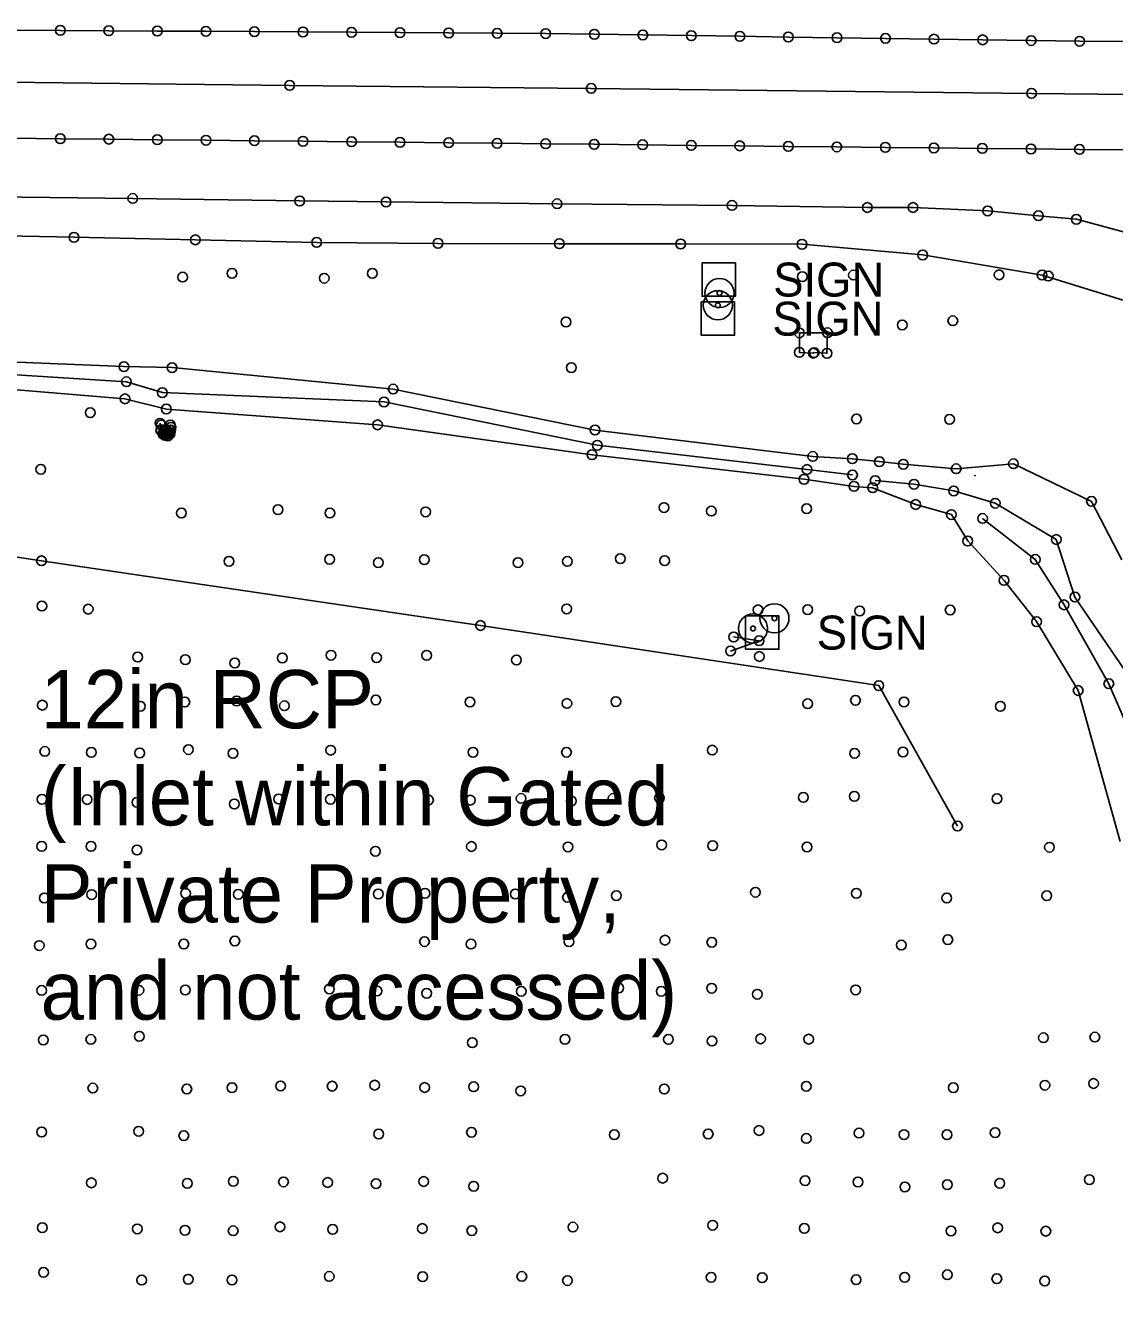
# Model space of a CAD drawing. Extents: x 20503438 to 20508873, y 7964251 to 7984667.
# Drawn here: x 20505827.9 to 20506052.3, y 7970296.1 to 7970558.9 of the extents above; entities that cross this region are included whole.
import ezdxf

# ---------------------------------------------------------------- set-up
doc = ezdxf.new("R2010")
doc.units = 0
for name, color, linetype in [('SurBreakLine', 7, 'Continuous'), ('SurConcreteSlab', 7, 'Continuous'), ('SurDrainageArrowDown', 7, 'Continuous'), ('SurDrainageArrowUp', 7, 'Continuous'), ('SurEdgeShoulderPaved', 7, 'Continuous'), ('SurEdgeShoulderUnpaved', 7, 'Continuous'), ('SurFenceChainLink', 7, 'Continuous'), ('SurMiscStructureLine', 7, 'Continuous'), ('SurPointsNonDTM', 7, 'Continuous'), ('SurRoadPoints', 7, 'Continuous'), ('SurSurveyPoints', 7, 'Continuous'), ('SurTopOfWater', 7, 'Continuous'), ('SurTxtDrainage', 7, 'Continuous')]:
    doc.layers.add(name, color=color, linetype=linetype)

msp = doc.modelspace()

# ---------------------------------------------------------------- linework, layer by layer
at = {"layer": 'SurBreakLine'}
for points in [[(20505659.98, 7970549.19), (20505725.91, 7970548.38), (20505788.99, 7970547.63), (20505882.34, 7970546.59), (20505944.46, 7970545.97), (20506035.17, 7970544.95), (20506055.65, 7970544.73), (20506135.76, 7970544.03), (20506246.7, 7970542.7), (20506314.1, 7970541.94), (20506377.13, 7970541.22), (20506448.59, 7970540.63), (20506494, 7970540.08), (20506513.48, 7970539.53), (20506534.35, 7970539.62)], [(20505710.77, 7970497.54), (20505732.85, 7970495.46), (20505756.48, 7970493.37), (20505802.57, 7970490.52), (20505848.21, 7970488.68), (20505858.14, 7970488.46), (20505903.67, 7970484.04), (20505945.27, 7970475.61), (20505990.11, 7970470.17), (20505998.24, 7970469.71), (20506003.81, 7970469.11), (20506008.75, 7970468.56), (20506019.64, 7970467.63), (20506031.44, 7970468.66), (20506047.52, 7970460.92), (20506053.76, 7970448.87)], [(20505711.46, 7970490.59), (20505731.01, 7970491.18), (20505758.81, 7970489.68), (20505801.32, 7970485.94), (20505848.43, 7970482.04), (20505856.97, 7970479.93), (20505900.46, 7970476.68), (20505944.64, 7970470.53), (20505988.31, 7970465.47), (20505998.59, 7970464), (20506002.44, 7970463.73), (20506011.31, 7970460.28), (20506018.66, 7970458.21), (20506022.02, 7970452.76), (20506029.51, 7970444.65), (20506036.2, 7970436.16), (20506044.77, 7970421.97), (20506053.42, 7970390.9)], [(20505857.84, 7970475.58), (20505857.72, 7970474.82), (20505857.29, 7970474.41), (20505856.69, 7970474.5), (20505856.27, 7970474.81), (20505855.82, 7970475.52), (20505855.65, 7970477.02)], [(20506002.96, 7970465.21), (20506010.95, 7970464.45), (20506019.15, 7970463.07), (20506027.69, 7970460.54), (20506040.26, 7970453.07), (20506044.1, 7970441.21), (20506055.37, 7970424.69), (20506067.63, 7970400.85), (20506090.73, 7970364.86), (20506121.5, 7970310.22), (20506143.59, 7970262.18), (20506176.03, 7970210.91), (20506203.05, 7970164.06), (20506235.78, 7970108.78), (20506259.31, 7970069.25), (20506303.96, 7969999.09)]]:
    msp.add_lwpolyline(points, dxfattribs=at)
at = {"layer": 'SurConcreteSlab'}
for points in [[(20506055.09, 7970555.65), (20506045.09, 7970555.68), (20506035.09, 7970555.82), (20506025.09, 7970555.97), (20506015.09, 7970556.11), (20506005.09, 7970556.26), (20505995.09, 7970556.4), (20505985.09, 7970556.55), (20505975.09, 7970556.69), (20505965.1, 7970556.83), (20505955.1, 7970556.98), (20505945.1, 7970557.12), (20505935.1, 7970557.26), (20505925.1, 7970557.32), (20505915.1, 7970557.39), (20505905.1, 7970557.45), (20505895.1, 7970557.52), (20505885.1, 7970557.59), (20505875.1, 7970557.65), (20505865.1, 7970557.72), (20505855.1, 7970557.78), (20505845.1, 7970557.85), (20505835.1, 7970557.92), (20505825.1, 7970557.98)], [(20505825.12, 7970535.72), (20505835.12, 7970535.61), (20505845.11, 7970535.51), (20505855.11, 7970535.4), (20505865.11, 7970535.3), (20505875.1, 7970535.19), (20505885.1, 7970535.08), (20505895.1, 7970534.98), (20505905.09, 7970534.87), (20505915.09, 7970534.77), (20505925.09, 7970534.66), (20505935.08, 7970534.56), (20505945.08, 7970534.45), (20505955.08, 7970534.35), (20505965.07, 7970534.24), (20505975.07, 7970534.14), (20505985.07, 7970534.03), (20505995.06, 7970533.92), (20506005.06, 7970533.82), (20506015.05, 7970533.71), (20506025.05, 7970533.61), (20506035.05, 7970533.5), (20506045.04, 7970533.4), (20506055.04, 7970533.3)], [(20505857.77, 7970476.64), (20505857.55, 7970475.22), (20505857.26, 7970474.83), (20505856.78, 7970474.8), (20505856.5, 7970474.91), (20505855.89, 7970476.65), (20505855.88, 7970475.71), (20505856.35, 7970474.81), (20505856.92, 7970474.72), (20505857.33, 7970474.73), (20505857.65, 7970474.96), (20505857.81, 7970475.61), (20505857.92, 7970476.17)]]:
    msp.add_lwpolyline(points, dxfattribs=at)
msp.add_lwpolyline([(20505993.14, 7970495.64), (20505987.36, 7970495.62), (20505987.35, 7970491.61), (20505990.21, 7970491.44), (20505990.39, 7970491.57), (20505993.03, 7970491.41)], close=True, dxfattribs=at)
at = {"layer": 'SurDrainageArrowDown'}
msp.add_lwpolyline([(20506025.08, 7970457.4), (20506035.95, 7970448.96), (20506041.86, 7970439.61), (20506051.09, 7970423.37), (20506062.05, 7970398.08), (20506083.83, 7970361.77), (20506117.02, 7970306.88), (20506136.1, 7970258.71), (20506172.77, 7970209.71), (20506199.46, 7970161.39), (20506230.82, 7970104.99), (20506255.2, 7970065.03), (20506302.09, 7969997.91), (20506332.16, 7969947.08), (20506370.3, 7969883.15), (20506398.2, 7969834.55), (20506432.94, 7969784.54)], dxfattribs=at)
at = {"layer": 'SurDrainageArrowUp'}
msp.add_lwpolyline([(20505588.51, 7970507.81), (20505597.53, 7970506.94), (20505614.51, 7970502.19), (20505635.08, 7970498.83), (20505655.93, 7970496.49), (20505678.23, 7970494.58), (20505682.9, 7970493.73), (20505711.11, 7970493.62), (20505731.16, 7970493.62), (20505757.46, 7970492.01), (20505802.13, 7970488.46), (20505848.74, 7970485.55), (20505856.14, 7970483.32), (20505901.79, 7970481.39), (20505945.72, 7970472.48), (20505988.92, 7970467.48), (20505998.29, 7970466.36)], dxfattribs=at)
at = {"layer": 'SurEdgeShoulderPaved'}
msp.add_lwpolyline([(20506056.08, 7970515.88), (20506044.41, 7970519.01), (20506036.59, 7970519.75), (20506026.15, 7970520.74), (20506010.77, 7970521.44), (20506001.36, 7970521.44), (20505973.47, 7970521.86), (20505937.45, 7970522.2), (20505902.22, 7970522.58), (20505884.4, 7970522.79), (20505850.04, 7970523.3), (20505804.42, 7970523.81), (20505772.68, 7970524.16), (20505723.75, 7970524.74), (20505698.34, 7970525.01)], dxfattribs=at)
at = {"layer": 'SurEdgeShoulderUnpaved'}
msp.add_lwpolyline([(20505583.75, 7970522.72), (20505588.05, 7970521.67), (20505613.04, 7970520.89), (20505638.02, 7970520.1), (20505663.01, 7970519.31), (20505687.99, 7970518.52), (20505712.98, 7970517.9), (20505737.97, 7970517.38), (20505762.96, 7970516.86), (20505787.95, 7970516.34), (20505812.95, 7970515.82), (20505837.94, 7970515.3), (20505862.93, 7970514.78), (20505887.92, 7970514.26), (20505912.91, 7970514.05), (20505937.9, 7970513.99), (20505962.89, 7970513.93), (20505987.89, 7970513.87), (20506012.76, 7970511.67), (20506037.35, 7970507.53), (20506060.92, 7970500.21), (20506079.1, 7970483.65), (20506094.14, 7970463.86), (20506101.05, 7970448.2)], dxfattribs=at)
at = {"layer": 'SurFenceChainLink'}
msp.add_lwpolyline([(20505563.79, 7970488.13), (20505618.36, 7970480.42), (20505698.84, 7970468.55), (20505760.89, 7970459.22), (20505831.24, 7970448.68), (20505921.66, 7970435.36), (20506003.71, 7970422.97), (20506019.92, 7970394.05)], dxfattribs=at)
at = {"layer": 'SurMiscStructureLine'}
msp.add_lwpolyline([(20505973.8, 7970432.99), (20505979.06, 7970432.22), (20505973.17, 7970430.1)], dxfattribs=at)
at = {"layer": 'SurPointsNonDTM'}
for centre in [(20505831.24, 7970448.68), (20505921.66, 7970435.36), (20505973.8, 7970432.99), (20505979.06, 7970432.22), (20505973.17, 7970430.1), (20506003.71, 7970422.97), (20506019.92, 7970394.05)]:
    msp.add_circle(centre, 1, dxfattribs=at)
at = {"layer": 'SurRoadPoints'}
for points in [[(20505970.75, 7970503.17), (20505970.75, 7970503.17), (20505974.18, 7970503.17), (20505974.18, 7970510.03), (20505967.32, 7970510.03), (20505967.32, 7970503.17), (20505970.75, 7970503.17)], [(20505970.57, 7970495.12), (20505970.57, 7970495.12), (20505974, 7970495.12), (20505974, 7970501.98), (20505967.14, 7970501.98), (20505967.14, 7970495.12), (20505970.57, 7970495.12)], [(20505979.71, 7970430.47), (20505979.71, 7970430.47), (20505983.14, 7970430.47), (20505983.14, 7970437.33), (20505976.28, 7970437.33), (20505976.28, 7970430.47), (20505979.71, 7970430.47)]]:
    msp.add_lwpolyline(points, dxfattribs=at)
for centre, radius in [((20505970.89, 7970503.83), 3), ((20505970.56, 7970501.31), 3), ((20505970.89, 7970503.83), 0.5), ((20505970.56, 7970501.31), 0.5), ((20505982.21, 7970436.84), 3), ((20505977.79, 7970434.74), 3), ((20505977.79, 7970434.74), 0.5), ((20505982.21, 7970436.84), 0.5)]:
    msp.add_circle(centre, radius, dxfattribs=at)
at = {"layer": 'SurSurveyPoints'}
for centre in [(20505835.1, 7970557.92), (20505845.1, 7970557.85), (20505855.1, 7970557.78), (20505865.1, 7970557.72), (20505875.1, 7970557.65), (20505885.1, 7970557.59), (20505895.1, 7970557.52), (20505905.1, 7970557.45), (20505915.1, 7970557.39), (20505925.1, 7970557.32), (20505935.1, 7970557.26), (20505945.1, 7970557.12), (20505955.1, 7970556.98), (20505965.1, 7970556.83), (20505975.09, 7970556.69), (20505985.09, 7970556.55), (20505995.09, 7970556.4), (20506005.09, 7970556.26), (20506015.09, 7970556.11), (20506025.09, 7970555.97), (20506035.09, 7970555.82), (20506045.09, 7970555.68), (20505882.34, 7970546.59), (20505944.46, 7970545.97), (20506035.17, 7970544.95), (20505835.12, 7970535.61), (20505845.11, 7970535.51), (20505855.11, 7970535.4), (20505865.11, 7970535.3), (20505875.1, 7970535.19), (20505885.1, 7970535.08), (20505895.1, 7970534.98), (20505905.09, 7970534.87), (20505915.09, 7970534.77), (20505925.09, 7970534.66), (20505935.08, 7970534.56), (20505945.08, 7970534.45), (20505955.08, 7970534.35), (20505965.07, 7970534.24), (20505975.07, 7970534.14), (20505985.07, 7970534.03), (20505995.06, 7970533.92), (20506005.06, 7970533.82), (20506015.05, 7970533.71), (20506025.05, 7970533.61), (20506035.05, 7970533.5), (20506045.04, 7970533.4), (20505850.04, 7970523.3), (20505884.4, 7970522.79), (20505902.22, 7970522.58), (20505937.45, 7970522.2), (20505973.47, 7970521.86), (20506001.36, 7970521.44), (20506010.77, 7970521.44), (20506026.15, 7970520.74), (20506036.59, 7970519.75), (20506044.41, 7970519.01), (20505837.94, 7970515.3), (20505862.93, 7970514.78), (20505887.92, 7970514.26), (20505912.91, 7970514.05), (20505937.9, 7970513.99), (20505962.89, 7970513.93), (20505987.89, 7970513.87), (20506012.76, 7970511.67), (20505870.48, 7970507.88), (20505899.38, 7970507.87), (20505860.3, 7970507.1), (20505889.47, 7970506.88), (20505987.96, 7970507.19), (20505998.49, 7970507.51), (20506028.49, 7970507.57), (20506037.35, 7970507.53), (20506038.6, 7970507.32), (20505939.29, 7970497.87), (20506008.53, 7970497.26), (20506018.96, 7970498.11), (20505987.36, 7970495.62), (20505993.14, 7970495.64), (20505987.35, 7970491.61), (20505990.21, 7970491.44), (20505990.39, 7970491.57), (20505993.03, 7970491.41), (20505848.21, 7970488.68), (20505858.14, 7970488.46), (20505940.36, 7970488.46), (20505848.74, 7970485.55), (20505848.43, 7970482.04), (20505856.14, 7970483.32), (20505903.67, 7970484.04), (20505841.27, 7970479.18), (20505856.97, 7970479.93), (20505901.79, 7970481.39), (20505855.65, 7970477.02), (20505855.89, 7970476.65), (20505857.77, 7970476.64), (20505900.46, 7970476.68), (20505999.11, 7970477.89), (20506018.28, 7970477.8), (20505855.82, 7970475.52), (20505855.88, 7970475.71), (20505856.27, 7970474.81), (20505856.35, 7970474.81), (20505856.5, 7970474.91), (20505856.69, 7970474.5), (20505856.78, 7970474.8), (20505856.92, 7970474.72), (20505857.26, 7970474.83), (20505857.29, 7970474.41), (20505857.33, 7970474.73), (20505857.55, 7970475.22), (20505857.65, 7970474.96), (20505857.72, 7970474.82), (20505857.81, 7970475.61), (20505857.84, 7970475.58), (20505857.92, 7970476.17), (20505945.27, 7970475.61), (20505945.72, 7970472.48), (20505944.64, 7970470.53), (20505990.11, 7970470.17), (20505998.24, 7970469.71), (20506003.81, 7970469.11), (20506008.75, 7970468.56), (20506031.44, 7970468.66), (20505831.09, 7970467.53), (20505988.92, 7970467.48), (20505998.29, 7970466.36), (20506019.64, 7970467.63), (20505988.31, 7970465.47), (20505998.59, 7970464), (20506002.44, 7970463.73), (20506002.96, 7970465.21), (20506010.95, 7970464.45), (20506019.15, 7970463.07), (20506027.69, 7970460.54), (20506047.52, 7970460.92), (20505860.07, 7970458.51), (20505879.96, 7970459.23), (20505890.64, 7970458.52), (20505910.36, 7970458.76), (20505959.48, 7970459.65), (20505969.2, 7970458.91), (20505988.86, 7970459.43), (20506011.31, 7970460.28), (20506018.66, 7970458.21), (20506025.08, 7970457.4), (20506022.02, 7970452.76), (20506040.26, 7970453.07), (20505869.88, 7970448.59), (20505890.57, 7970448.98), (20505900.62, 7970448.31), (20505910.09, 7970448.91), (20505929.37, 7970448.32), (20505939.57, 7970448.55), (20505950.48, 7970449.13), (20505959.59, 7970448.7), (20506035.95, 7970448.96), (20506029.51, 7970444.65), (20506041.86, 7970439.61), (20506044.1, 7970441.21), (20505831.32, 7970439.36), (20505840.86, 7970438.72), (20505939.42, 7970438.78), (20505978.84, 7970438.58), (20505989.04, 7970438.63), (20505999.78, 7970438.35), (20506018.41, 7970438.54), (20506036.2, 7970436.16), (20505890.85, 7970429.24), (20505910.59, 7970429.21), (20505979.1, 7970428.97), (20505851.04, 7970428.87), (20505860.88, 7970428.32), (20505871.05, 7970427.65), (20505880.84, 7970428.67), (20505900.25, 7970428.72), (20505929.07, 7970428.25), (20506044.77, 7970421.97), (20506051.09, 7970423.37), (20505831.39, 7970418.95), (20505851.6, 7970418.73), (20505860.76, 7970419.6), (20505871.43, 7970419.83), (20505881.28, 7970418.82), (20505900.11, 7970420.03), (20505919.48, 7970419.59), (20505939.46, 7970419.3), (20505949.55, 7970419.68), (20505989.07, 7970419.24), (20505998.91, 7970419.95), (20506008.91, 7970419.6), (20506028.74, 7970418.71), (20505831.92, 7970409.42), (20505841.49, 7970409.22), (20505851.45, 7970409.1), (20505861.51, 7970409.81), (20505870.7, 7970409.02), (20505890.81, 7970409.68), (20505920.1, 7970409.24), (20505939.38, 7970409.25), (20505969.39, 7970409.69), (20505998.71, 7970409.02), (20506008.71, 7970409.29), (20505998.65, 7970400.18), (20505831.34, 7970399.55), (20505840.64, 7970399.52), (20505850.9, 7970398.94), (20505870.94, 7970398.6), (20505880.11, 7970399.62), (20505890.76, 7970399.54), (20505910.95, 7970399.41), (20505919.57, 7970399.39), (20505930.03, 7970399.74), (20505940.37, 7970399.22), (20505948.98, 7970399.74), (20505958.53, 7970399.84), (20505988.16, 7970399.96), (20506028.07, 7970399.69), (20505831.28, 7970389.86), (20505841.42, 7970389.88), (20505919.8, 7970389.85), (20505939.7, 7970389.77), (20505959, 7970390.18), (20505969.47, 7970390), (20505988.93, 7970389.75), (20506038.86, 7970389.7), (20505850.9, 7970389.11), (20505900.03, 7970388.87), (20505831.84, 7970379.26), (20505841.57, 7970379.95), (20505860.91, 7970380.21), (20505871.78, 7970379.98), (20505900.63, 7970380.07), (20505910.23, 7970380.2), (20505928.86, 7970380.08), (20505939.58, 7970379.37), (20505949.64, 7970379.74), (20505978.3, 7970380.43), (20505999.09, 7970380.22), (20506017.71, 7970379.24), (20506038.31, 7970379.71), (20505830.77, 7970369.45), (20505841.41, 7970369.75), (20505860.56, 7970369.76), (20505871.06, 7970370.38), (20505910.13, 7970370.27), (20505919.7, 7970369.74), (20505939.88, 7970370.24), (20505959.67, 7970370.56), (20505969.31, 7970370.13), (20506008.35, 7970369.54), (20506017.93, 7970370.67), (20505950.14, 7970360.71), (20505969.27, 7970360.66), (20505831.28, 7970360.2), (20505851.3, 7970360.25), (20505860.86, 7970360.29), (20505890.55, 7970360.51), (20505900.36, 7970360.1), (20505910.57, 7970359.62), (20505930.05, 7970360.04), (20505958.89, 7970360.04), (20505978.69, 7970359.43), (20505998.95, 7970360.32), (20505841.4, 7970350.11), (20505851.38, 7970350.75), (20505939.07, 7970350.12), (20505960.38, 7970350.13), (20505979.35, 7970350.24), (20505989.25, 7970350.17), (20506037.62, 7970350.45), (20506048.21, 7970350.59), (20505831.62, 7970350.01), (20505920, 7970349.45), (20505969.37, 7970349.77), (20505841.81, 7970340.09), (20505861.17, 7970339.91), (20505870.49, 7970340.2), (20505880.48, 7970340.53), (20505891.11, 7970340.49), (20505899.86, 7970340.7), (20505910.16, 7970340.22), (20505920.24, 7970340.36), (20505959.51, 7970339.91), (20505988.76, 7970340.47), (20506019.08, 7970340.17), (20506037.92, 7970340.69), (20506047.94, 7970341.04), (20505929.95, 7970339.52), (20505831.29, 7970331.05), (20505851.24, 7970331.21), (20505860.56, 7970330.3), (20505900.68, 7970330.62), (20505919.81, 7970330.99), (20505949.23, 7970330.5), (20505968.56, 7970330.64), (20505979.05, 7970331.36), (20505988.77, 7970329.72), (20505999.62, 7970330.82), (20506008.9, 7970330.53), (20506017.76, 7970330.5), (20506027.67, 7970330.91), (20505959.2, 7970321.54), (20506047.09, 7970321.24), (20505841.51, 7970320.58), (20505861.28, 7970320.47), (20505870.75, 7970320.91), (20505881.09, 7970320.78), (20505890.19, 7970320.65), (20505900.16, 7970320.41), (20505909.96, 7970320.86), (20505920.27, 7970319.88), (20505988.53, 7970321.02), (20505999.41, 7970320.77), (20506009.08, 7970319.74), (20506017.81, 7970320.22), (20506028.63, 7970320.47), (20505831.41, 7970311.34), (20505850.97, 7970311.1), (20505860.79, 7970310.81), (20505870.72, 7970310.71), (20505880.36, 7970311.52), (20505891.2, 7970310.99), (20505909.7, 7970311.18), (20505919.88, 7970310.74), (20505940.69, 7970311.46), (20505969.49, 7970311.86), (20505988.38, 7970311.2), (20506028.2, 7970311.32), (20506018.56, 7970310.67), (20506038.11, 7970310.63), (20505831.66, 7970302.14), (20505851.89, 7970300.55), (20505861.46, 7970300.73), (20505870.47, 7970300.57), (20505890.5, 7970301.3), (20505909.75, 7970301.25), (20505930.18, 7970301.3), (20505939.58, 7970300.46), (20505969.17, 7970301.13), (20505979.69, 7970301.05), (20505999.04, 7970300.63), (20506009.04, 7970301.13), (20506017.83, 7970301.65), (20506028.02, 7970300.83), (20506037.9, 7970300.37)]:
    msp.add_circle(centre, 1, dxfattribs=at)
at = {"layer": 'SurTopOfWater'}
for points in [[(20506023.5, 7970466.21), (20506023.54, 7970466.21), (20506023.54, 7970466.25), (20506023.5, 7970466.25)], [(20506023.52, 7970466.26), (20506023.52, 7970466.26), (20506023.52, 7970466.22), (20506023.52, 7970466.22)], [(20506023.52, 7970466.26), (20506023.52, 7970466.26), (20506023.52, 7970466.24), (20506023.52, 7970466.24)], [(20506023.52, 7970466.24), (20506023.52, 7970466.24), (20506023.52, 7970466.23), (20506023.52, 7970466.23)], [(20506023.52, 7970466.23), (20506023.52, 7970466.23), (20506023.52, 7970466.22), (20506023.52, 7970466.22)], [(20506043.91, 7970421.49), (20506043.95, 7970421.49), (20506043.95, 7970421.53), (20506043.91, 7970421.53)], [(20506043.93, 7970421.54), (20506043.93, 7970421.54), (20506043.93, 7970421.5), (20506043.93, 7970421.5)], [(20506043.93, 7970421.54), (20506043.93, 7970421.54), (20506043.93, 7970421.52), (20506043.93, 7970421.52)], [(20506043.93, 7970421.52), (20506043.93, 7970421.52), (20506043.93, 7970421.51), (20506043.93, 7970421.51)], [(20506043.93, 7970421.51), (20506043.93, 7970421.51), (20506043.93, 7970421.5), (20506043.93, 7970421.5)]]:
    msp.add_lwpolyline(points, close=True, dxfattribs=at)
for centre in [(20506023.51, 7970466.23), (20506023.52, 7970466.23), (20506023.53, 7970466.23), (20506043.92, 7970421.51), (20506043.93, 7970421.51), (20506043.94, 7970421.51)]:
    msp.add_arc(centre, 0.00586, 186.3566, 5.6839, dxfattribs=at)

# ---------------------------------------------------------------- texts
at = {"layer": 'SurRoadPoints'}
for p in [(20505981.96, 7970503.1), (20505981.78, 7970495.05), (20505990.92, 7970430.4)]:
    msp.add_text('SIGN', height=6.995, rotation=360, dxfattribs=at).set_placement(p)
at = {"layer": 'SurTxtDrainage'}
for s, p in [('12in RCP', (20505831.05, 7970414.19)), ('(Inlet within Gated', (20505831.05, 7970394.19)), ('Private Property, ', (20505831.05, 7970374.19)), ('and not accessed)', (20505831.05, 7970354.19))]:
    msp.add_text(s, height=12, dxfattribs=at).set_placement(p)

doc.saveas('drawing.dxf')
